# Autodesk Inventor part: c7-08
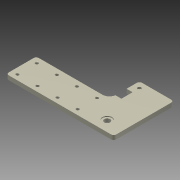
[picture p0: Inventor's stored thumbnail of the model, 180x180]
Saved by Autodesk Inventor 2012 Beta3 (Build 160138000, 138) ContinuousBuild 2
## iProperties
Created: 2010-12
Part Number: c7-08
Material: Steel
Document SubType Name: Modeling
Designer: Beta-8540w
Mass: 1769.34 g
Surface Area: 558.866 cm^2
Volume: 225.394 cm^3
Density: 7.85 g/cm^3
Author: Beta-8540w
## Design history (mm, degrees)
sketch "Sketch1"
  geometry: L1 (0, 0)-(250, 0); L2 (250, 0)-(250, 70); L3 (250, 70)-(0, 70); L4 (0, 70)-(0, 0); L5 (250, 70)-(170, 70); L6 (170, 70)-(170, 140); L7 (170, 140)-(250, 140); L8 (250, 140)-(250, 70)
  constraints: 16 end point, 4 parallel, 2 horizontal, 2 perpendicular
  dimensions: "d0" = 250 distance of L3.end L2.end; "d1" = 70 distance of L2.end L1.end; "d2" = 80 distance of L6.end L7.end; "d3" = 70 distance of L5.end L6.end
extrude "Extrusion1" new body sketch "Sketch1" distance "d4" = 10; taper "d5" = 0 deg
sketch "Sketch4"
  geometry: L1 (250, 140)-(170, 140) reference; L2 (170, 140)-(170, 70) reference; L3 (170, 84)-(184, 84); L4 (184, 84)-(184, 110); L5 (184, 110)-(170, 110); L6 (170, 110)-(170, 84)
  constraints: 8 end point, 2 parallel, 1 horizontal, 1 perpendicular, 1 point on line
  dimensions: "d41" = 14 distance of L5.end L4.end; "d42" = 26 distance of L4.end L3.end; "d43" = 30 distance between parallel lines of L1 L5
extrude "Extrusion2" cut sketch "Sketch4" stored distance "d44" = 10; taper "d45" = 0 deg
sketch "Sketch2"
  geometry: L1 (0, 70)-(0, 0) reference; L2 (14, 12.5)-(154, 12.5); L3 (154, 12.5)-(154, 57.5); L4 (154, 57.5)-(14, 57.5); L5 (14, 57.5)-(14, 12.5); L6 (60.667, 57.5)-(60.667, 12.5); L7 (107.333, 57.5)-(107.333, 12.5); 2 further points
  constraints: 12 end point, 4 point on line, 3 perpendicular, 2 midpoint, 2 parallel, 1 horizontal, 1 horizontal alignment
  dimensions: "d6" = 140 distance of L4.end L3.end; "d7" = 45 distance of L3.end L2.end; "d8" = 46.66667 distance between parallel lines of L6 L5 (= 0.333333 x d6); "d9" = 46.66667 distance between parallel lines of L7 L6 (= d8); "d10" = 14 distance between parallel lines of L1 L5
hole "Hole1" sketch "Sketch2" at (14, 12.5), (154, 57.5), (154, 12.5), (14, 57.5), (60.667, 57.5), (60.667, 12.5), (107.333, 57.5), (107.333, 12.5) diameter "d11" = 6.6; stored, may be unused: countersink angle "d15" = 90 deg, drill point angle "d17" = 118 deg; dims "d12" = 6, "d13" = 4, "d14" = 90, "d16" = 8
hole "Hole3" diameter "d52" = 3.242; stored, may be unused: countersink angle "d56" = 90 deg, drill point angle "d58" = 118 deg; dims "d50" = 43, "d51" = 5, "d53" = 8, "d54" = 4, "d55" = 2, "d57" = 10
fillet "Fillet1" dims "d39" = 6, "d46" = 1
fillet "Fillet2" dims "d40" = 16
chamfer "Chamfer1" distance "d47" = 0.5; stored, may be unused: second distance "d48" = 2, angle "d49" = 45 deg
chamfer "Chamfer2" distance "d59" = 0.5; stored, may be unused: second distance "d60" = 2, angle "d61" = 45 deg
hole "Hole6" diameter "d74" = 4.5; stored, may be unused: countersink angle "d78" = 90 deg, drill point angle "d80" = 118 deg; dims "d72" = 14, "d73" = 14, "d75" = 6, "d76" = 8, "d77" = 4, "d79" = 8
body "Solid1"
hole "Hole2" diameter "d32" = 13.492; stored, may be unused: countersink angle "d36" = 90 deg, drill point angle "d38" = 118 deg; dims "d30" = 40, "d31" = 25, "d33" = 6, "d34" = 22.225, "d35" = 2, "d37" = 8
